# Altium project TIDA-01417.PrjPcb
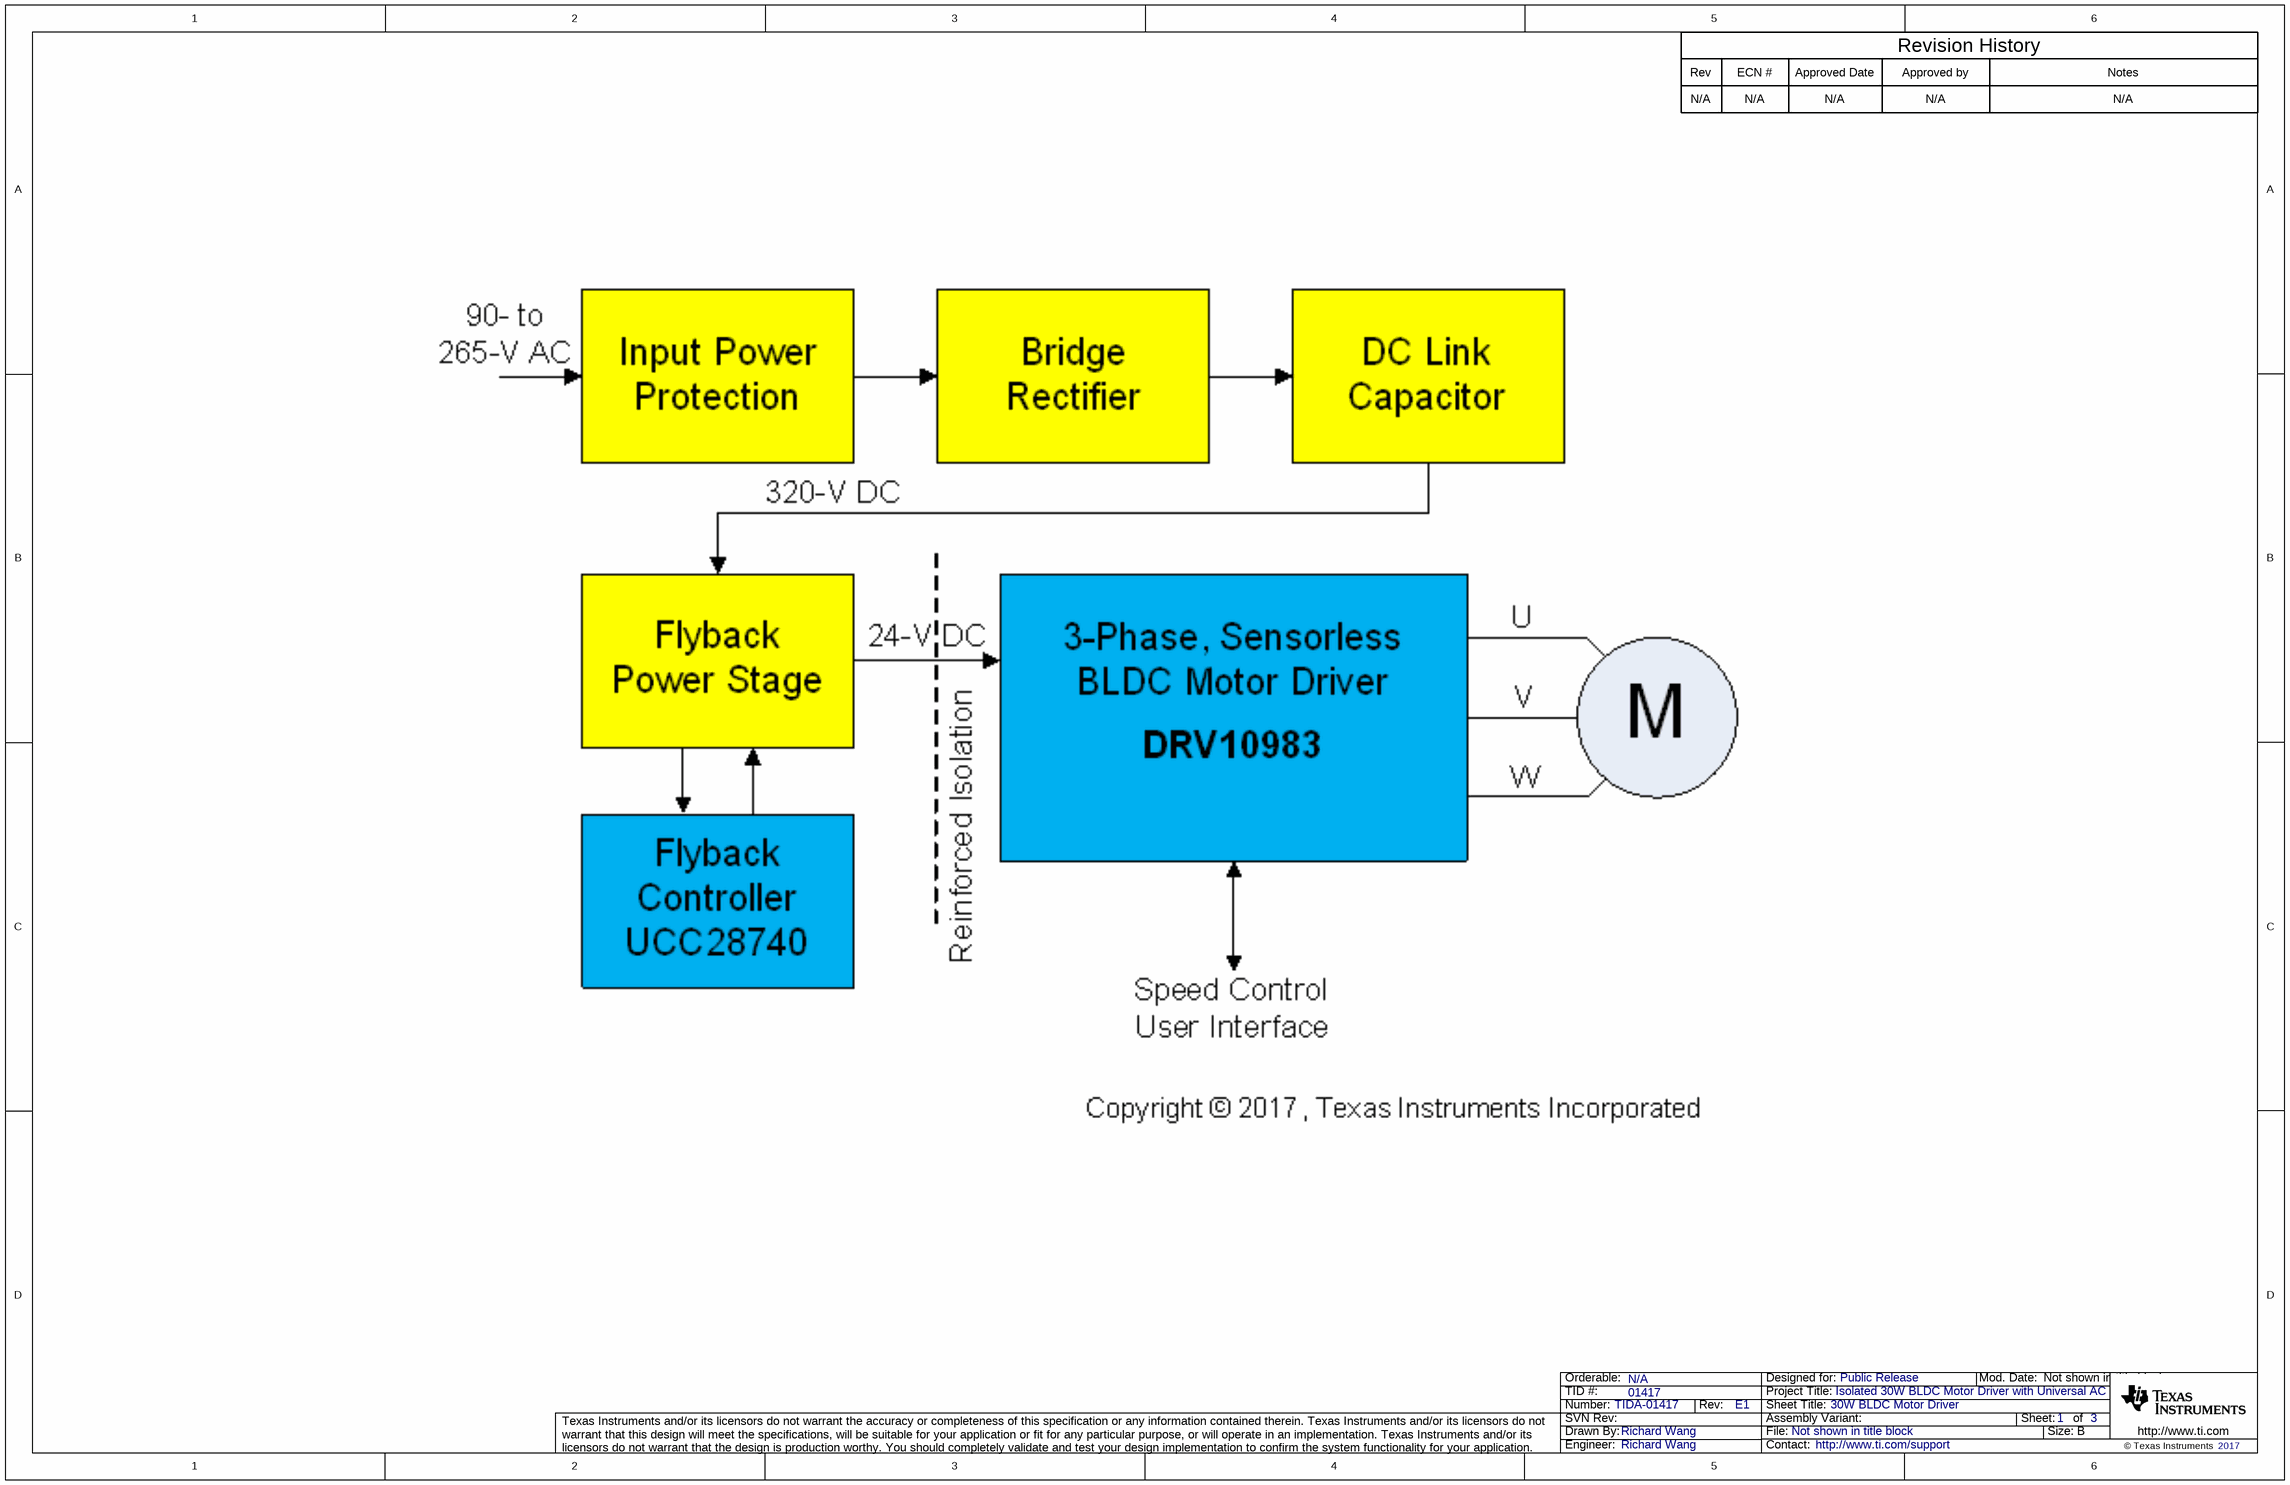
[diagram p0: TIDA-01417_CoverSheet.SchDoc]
CopyrightYear: 2017; EVM_orderable: N/A; PCB_Layout: Richard Wang; PCB_Rev: E1; PRJ_Customer: Public Release; PRJ_Engineer: Richard Wang; PRJ_Number: TIDA-01417; PRJ_Title: Isolated 30W BLDC Motor Driver with Universal AC input; SCH_Rev: E1; TechSupport: http://www.ti.com/support; TID: 01417
3 sheets, 70 parts. Net scope: flat (ports and power ports of the same name join across sheets).
Board file: TIDA-01417_PCB.PcbDoc
Sheets:
  TIDA-01417_CoverSheet.SchDoc
  TIDA-01417_BlankSheet.SchDoc
  TIDA-01417_EVM_Hardware.SchDoc

## Sheet TIDA-01417_CoverSheet.SchDoc: 30W BLDC Motor Driver
size 431 x 279 mm; Date: Not shown in title block; ApprovedBy: Not shown in title block; CheckedBy: Not shown in title block; Author: Not shown in title block; CompanyName: Not shown in title block; DrawnBy: Richard Wang; Engineer: Not shown in title block; Organization: Not shown in title block; Address1: Not shown in title block; Address2: Not shown in title block; Address3: Not shown in title block; Address4: Not shown in title block; DocumentNumber: 1; Revision: Use project parameter SCH_Rev; SheetNumber: 1; SheetTotal: 3; PageSetup: Record=PageOptions¦CenterHorizontal=True¦CenterVertical=True¦PrintScale=1.00¦XCorrection=1.00¦YCorrection=1.00¦PrintKind=0¦BorderSize=5000000¦LeftOffset=0¦BottomOffset=0¦Orientation=2¦PaperLength=1000¦PaperWidth=1000¦Scale=100¦PaperSource=15¦PrintQuality=600¦MediaType=1¦DitherType=10¦PaperKind=Letter¦PrintScaleMode=1

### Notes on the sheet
- Rev
- N/A
- ECN #
- Approved Date
- Approved by
- Revision History
- Notes

## Sheet TIDA-01417_BlankSheet.SchDoc: Isolated 30W BLDC Motor Driver
size 431 x 279 mm; Date: Not shown in title block; ApprovedBy: Not shown in title block; CheckedBy: Not shown in title block; Author: Not shown in title block; CompanyName: Not shown in title block; DrawnBy: Richard Wang; Engineer: Not shown in title block; Organization: Not shown in title block; Address1: Not shown in title block; Address2: Not shown in title block; Address3: Not shown in title block; Address4: Not shown in title block; DocumentNumber: 1; Revision: Use project parameter SCH_Rev; SheetNumber: 2; SheetTotal: 3; PageSetup: Record=PageOptions¦CenterHorizontal=True¦CenterVertical=True¦PrintScale=1.00¦XCorrection=1.00¦YCorrection=1.00¦PrintKind=0¦BorderSize=5000000¦LeftOffset=0¦BottomOffset=0¦Orientation=2¦PaperLength=1000¦PaperWidth=1000¦Scale=100¦PaperSource=15¦PrintQuality=600¦MediaType=1¦DitherType=10¦PaperKind=Letter¦PrintScaleMode=1
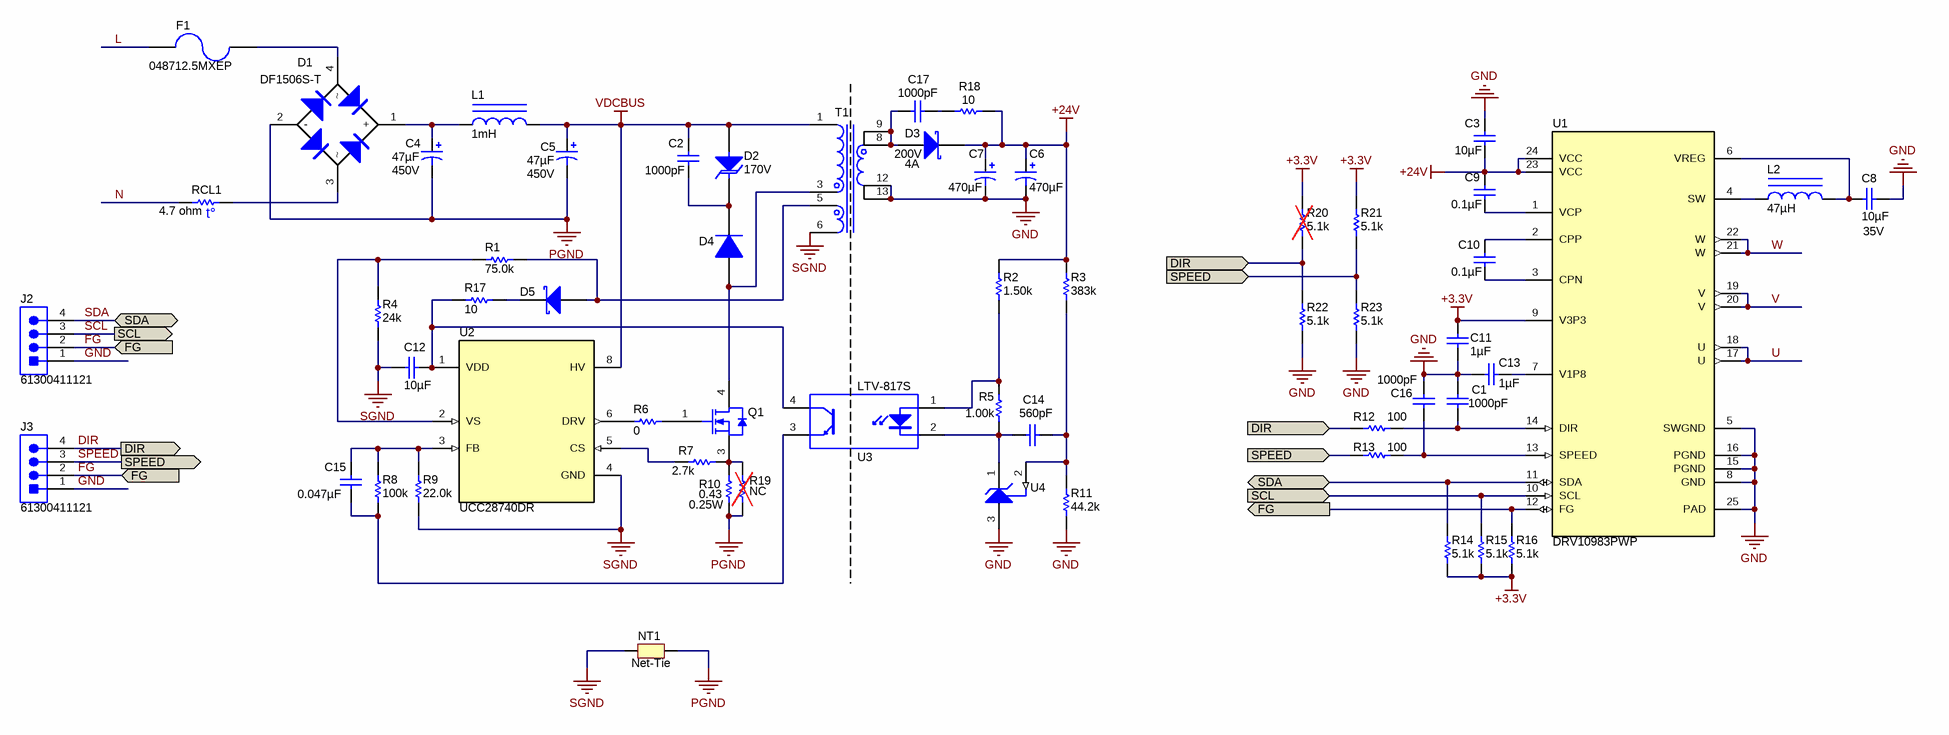
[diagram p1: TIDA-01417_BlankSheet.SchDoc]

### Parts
C1  ValueDisplayed: 1000pF  [0603]  (hidden comment: CGA3E2X7R2A102K080AA)
C2  ValueDisplayed: 1000pF  [0805_HV]  (hidden comment: C0805C102JBRACTU)
C3  ValueDisplayed: 10µF  [0805_HV]  (hidden comment: C2012X5R1V106K085AC)
C4  ValueDisplayed: 47µF  Value2: 450V  [SMG_1600x3550]  (hidden comment: ESMG451ELL470MLP1S)
C5  ValueDisplayed: 47µF  Value2: 450V  [SMG_1600x3550]  (hidden comment: ESMG451ELL470MLP1S)
C6  ValueDisplayed: 470µF  [Chemi-Con_1000x2000]  (hidden comment: ELXZ350ELL471MJ20S)
C7  ValueDisplayed: 470µF  [Chemi-Con_1000x2000]  (hidden comment: ELXZ350ELL471MJ20S)
C8  ValueDisplayed: 10µF  Value2: 35V  [0805_HV]  (hidden comment: C2012X5R1V106K085AC)
C9  ValueDisplayed: 0.1µF  [0603]  (hidden comment: C1608X5R1H104K080AA)
C10  ValueDisplayed: 0.1µF  [0603]  (hidden comment: C1608X5R1H104K080AA)
C11  ValueDisplayed: 1µF  [0603]  (hidden comment: C1608X5R1H105K080AB)
C12  ValueDisplayed: 10µF  [0805_HV]  (hidden comment: C2012X5R1V106K085AC)
C13  ValueDisplayed: 1µF  [0603]  (hidden comment: C1608X5R1H105K080AB)
C14  ValueDisplayed: 560pF  [0603]  (hidden comment: GRM188R71H561KA01D)
C15  ValueDisplayed: 0.047µF  [0603]  (hidden comment: C1608X5R1H473K080AA)
C16  ValueDisplayed: 1000pF  [0603]  (hidden comment: CGA3E2X7R2A102K080AA)
C17  ValueDisplayed: 1000pF  [0805_HV]  (hidden comment: C0805C102JBRACTU)
D1  DF1506S-T  [DF-S]
D2  value 170V  [SMB]  (hidden comment: SMBJ170A-13-F)
D3  value 200V  Value1: 4A  [SMC]  (hidden comment: MBRS4201T3G)
D4  US1M-13-F  [SMA]  (value not drawn)
D5  PMEG10010ELRX  [SOD-123W]  (value not drawn)
F1  048712.5MXEP  [Fuse_217_015_Verical]
J2  61300411121  [WURTH_61300411121]
J3  61300411121  [WURTH_61300411121]
L1  ValueDisplayed: 1mH  [WE-TI_8095]  (hidden comment: 768772102)
L2  ValueDisplayed: 47µH  [IND_CB2518]  (hidden comment: CB2518T470K)
NT1  Net-Tie  [Net-Tie_10mil]  (net tie, no BOM)
Q1  TK7P65W,RQ  [DPAK]  (value not drawn)
R1  ValueDisplayed: 75.0k  [0603]  (hidden comment: RC0603FR-0775KL)
R2  ValueDisplayed: 1.50k  [0603]  (hidden comment: RC0603FR-071K5L)
R3  ValueDisplayed: 383k  [0603]  (hidden comment: RT0603BRD07383KL)
R4  ValueDisplayed: 24k  [0603]  (hidden comment: RC0603JR-0724KL)
R5  ValueDisplayed: 1.00k  [0603]  (hidden comment: RC0603FR-071KL)
R6  ValueDisplayed: 0  [0603]  (hidden comment: MCR03EZPJ000)
R7  ValueDisplayed: 2.7k  [0603]  (hidden comment: RC0603JR-072K7L)
R8  ValueDisplayed: 100k  [0603]  (hidden comment: RC0603FR-07100KL)
R9  ValueDisplayed: 22.0k  [0603]  (hidden comment: RC0603FR-0722KL)
R10  ValueDisplayed: 0.43  Value2: 0.25W  [1206]  (hidden comment: ERJ-8RQFR43V)
R11  ValueDisplayed: 44.2k  [0603]  (hidden comment: RC0603FR-0744K2L)
R12  ValueDisplayed: 100  [0603]  (hidden comment: RC0603FR-07100RL)
R13  ValueDisplayed: 100  [0603]  (hidden comment: RC0603FR-07100RL)
R14  ValueDisplayed: 5.1k  [0603]  (hidden comment: RC0603JR-075K1L)
R15  ValueDisplayed: 5.1k  [0603]  (hidden comment: RC0603JR-075K1L)
R16  ValueDisplayed: 5.1k  [0603]  (hidden comment: RC0603JR-075K1L)
R17  ValueDisplayed: 10  [0603]  (hidden comment: CRCW060310R0JNEA)
R18  ValueDisplayed: 10  [0805_HV]  (hidden comment: RC0805JR-0710RL)
R19  NC  [1206]
R20  ValueDisplayed: 5.1k  [0603]  (hidden comment: RC0603JR-075K1L)
R21  ValueDisplayed: 5.1k  [0603]  (hidden comment: RC0603JR-075K1L)
R22  ValueDisplayed: 5.1k  [0603]  (hidden comment: RC0603JR-075K1L)
R23  ValueDisplayed: 5.1k  [0603]  (hidden comment: RC0603JR-075K1L)
RCL1  value 4.7 ohm  [THERM_B57236S0]  (hidden comment: B57236S479M)
T1  750343466  [PCBComponent_1]  (value not drawn)
U1  DRV10983PWP  [PWP0024B_N]
U2  UCC28740DR  [D0007A_N]
U3  LTV-817S  [DIP254P762X350-4]
U4  TL431BQDBZT  [DBZ0003A_N]  (value not drawn)

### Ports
DIR (in), DIR (out), FG (in), FG (out), SCL (in), SCL (out), SDA (bidir), SPEED (in), SPEED (out)

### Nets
+3.3V: C11.2 R14.1 R15.1 R16.1 R20.2 R21.2 U1.9(V3P3)
+24V: C3.2 C6.1(+) C7.1(+) C9.2 D3.1(K) R2.2 R3.2 R18.2 U1.23(VCC) U1.24(VCC)
GND: C1.1 C3.1 C6.2(-) C7.2(-) C8.1 C11.1 C13.1 C16.1 J2.1 J3.1 R11.1 R22.1 R23.1 T1.12 T1.13 U1.5(SWGND) U1.8(GND) U1.15(PGND) U1.16(PGND) U1.25(PAD) U4.3(ANODE)
PGND: C4.2(-) C5.2(-) D1.2(-) NT1.2 R10.1 R19.1
SGND: C12.1 NT1.1 R4.1 R9.1 T1.6 U2.4(GND)
VDCBUS: C2.1 C5.1(+) D2.2(A) L1.2 T1.1 U2.8(HV)
DIR: J3.4 R12.1 R20.1 R22.2 ; port DIR
FG: J2.2 J3.2 R16.2 U1.12(FG) ; port FG
L: F1.1
N: RCL1.1
SCL: J2.3 R15.2 U1.10(SCL) ; port SCL
SDA: J2.4 R14.2 U1.11(SDA) ; port SDA
SPEED: J3.3 R13.1 R21.1 R23.2 ; port SPEED
U: U1.17(U) U1.18(U)
V: U1.19(V) U1.20(V)
W: U1.21(W) U1.22(W)
NetC1_2: C1.2 R12.2 U1.14(DIR)
NetC2_2: C2.2 D2.1(K) D4.1(K)
NetC4_1: C4.1(+) D1.1(+) L1.1
NetC8_2: C8.2 L2.2 U1.6(VREG)
NetC9_1: C9.1 U1.1(VCP)
NetC10_1: C10.1 U1.2(CPP)
NetC10_2: C10.2 U1.3(CPN)
NetC12_2: C12.2 R17.1 U2.1(VDD) U3.4(C)
NetC13_2: C13.2 U1.7(V1P8)
NetC14_1: C14.1 R3.1 R11.2 U4.2(REF)
NetC14_2: C14.2 R5.1 U3.2(K) U4.1(CATHODE)
NetC15_1: C15.1 R8.2 R9.2 U2.3(FB)
NetC15_2: C15.2 R8.1 U3.3(E)
NetC16_2: C16.2 R13.2 U1.13(SPEED)
NetC17_1: C17.1 D3.2(A) T1.8 T1.9
NetC17_2: C17.2 R18.1
NetD1_3: D1.3 RCL1.2
NetD1_4: D1.4 F1.2
NetD4_2: D4.2(A) Q1.4(D) T1.3
NetD5_1: D5.1(K) R17.2
NetD5_2: D5.2(A) R1.2 T1.5
NetL2_1: L2.1 U1.4(SW)
NetQ1_1: Q1.1(G) R6.2
NetQ1_3: Q1.3(S) R7.2 R10.2 R19.2
NetR1_1: R1.1 R4.2 U2.2(VS)
NetR2_1: R2.1 R5.2 U3.1(A)
NetR6_1: R6.1 U2.6(DRV)
NetR7_1: R7.1 U2.5(CS)

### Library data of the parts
C1 C16 = CGA3E2X7R2A102K080AA: CAP, CERM, 1000 pF, 100 V, +/- 10%, X7R, AEC-Q200 Grade 1, 0603; Manufacturer: TDK; Polarized: N; CompType: Capacitor; Value: 1000pF; U/M: EA; Cap_F: 0.000000001; Tolerance_%: 10; ESR_ohm: 1.97137; Value1: 1.97137 ohm; VDC_V: 100; Value2: 100V; IRMS_A: 0.305705; TaMin_C: -55; TaMax_C: 125; SizeArea_mm2: 1.28; SizeAreaWB_mm2: 4.68; SizeX_mm: 1.6; SizeY_mm: 0.8; SizeZ_mm: 1; AEC Category: Q200; AEC Qualified: Y
C2 C17 = C0805C102JBRACTU: CAP, CERM, 1000 pF, 630 V, +/- 5%, X7R, 0805; Manufacturer: Kemet; Polarized: N; CompType: Capacitor; Value: 1000pF; U/M: EA; Cap_F: 0.000000001; Tolerance_%: 5; Value1: Unknown; VDC_V: 630; Value2: 630V; TaMin_C: -55; TaMax_C: 125; Cap_Case: 0805; SizeArea_mm2: 2.5; SizeAreaWB_mm2: 6.75; SizeX_mm: 2; SizeY_mm: 1.25; SizeZ_mm: 1.45; AEC Category: Q200
C3 C12 = C2012X5R1V106K085AC: CAP, CERM, 10 µF, 35 V, +/- 10%, X5R, 0805; Manufacturer: TDK; Polarized: N; CompType: Capacitor; Value: 10uF; U/M: EA; Cap_F: 0.00001; Tolerance_%: 10; ESR_ohm: 0.002818; Value1: 0.002818 ohm; VDC_V: 35; Value2: 35V; IRMS_A: 3.88676; TaMin_C: -55; TaMax_C: 85; Cap_Case: 0805; SizeArea_mm2: 2.5; SizeAreaWB_mm2: 6.75; SizeX_mm: 2; SizeY_mm: 1.25; SizeZ_mm: 1.45; AEC Category: Q200
C4 C5 = ESMG451ELL470MLP1S: CAP, AL, 47 µF, 450 V, +/- 20%, TH; Manufacturer: Chemi-Con; Polarized: Y; CompType: Capacitor; Value: 47uF; U/M: EA; Cap_F: 0.000047; Tolerance_%: 20; Value1: Unknown; VDC_V: 450; IRMS_A: 0.265; TaMin_C: -25; TaMax_C: 85; Cap_Case: 16x35.5mm; SizeAreaWB_mm2: 324; SizeArea_mm2: 256; SizeX_mm: 16; SizeZ_mm: 37; AEC Category: Q200; AEC Qualified: N
C6 C7 = ELXZ350ELL471MJ20S: CAP, AL, 470 µF, 35 V, +/- 20%, AEC-Q200 Grade 2, TH; Manufacturer: Chemi-Con; Polarized: Y; CompType: Capacitor; Value: 470uF; U/M: EA; Cap_F: 0.00047; Tolerance_%: 20; Value1: Unknown; VDC_V: 35; Value2: 35V; IRMS_A: 1.22; TaMin_C: -55; TaMax_C: 105; Cap_Case: 10x20mm; SizeAreaWB_mm2: 144; SizeArea_mm2: 100; SizeX_mm: 10; SizeZ_mm: 21.5; AEC Category: Q200; AEC Grade: 2
C8 = C2012X5R1V106K085AC: CAP, CERM, 10 µF, 35 V, +/- 10%, X5R, 0805; Manufacturer: TDK; Polarized: N; CompType: Capacitor; Value: 10uF; U/M: EA; Cap_F: 0.00001; Tolerance_%: 10; ESR_ohm: 0.002818; Value1: 0.002818 ohm; VDC_V: 35; IRMS_A: 3.88676; TaMin_C: -55; TaMax_C: 85; Cap_Case: 0805; SizeArea_mm2: 2.5; SizeAreaWB_mm2: 6.75; SizeX_mm: 2; SizeY_mm: 1.25; SizeZ_mm: 1.45; AEC Category: Q200
C9 C10 = C1608X5R1H104K080AA: CAP, CERM, 0.1 µF, 50 V, +/- 10%, X5R, 0603; Manufacturer: TDK; Polarized: N; CompType: Capacitor; Value: 0.1uF; U/M: EA; Cap_F: 0.0000001; Tolerance_%: 10; ESR_ohm: 0.0296; Value1: 0.0296 ohm; VDC_V: 50; Value2: 50V; IRMS_A: 0.97199; TaMin_C: -55; TaMax_C: 85; SizeArea_mm2: 1.28; SizeAreaWB_mm2: 4.68; SizeX_mm: 1.6; SizeY_mm: 0.8; SizeZ_mm: 1; AEC Category: Q200
C11 C13 = C1608X5R1H105K080AB: CAP, CERM, 1 µF, 50 V, +/- 10%, X5R, 0603; Manufacturer: TDK; Polarized: N; CompType: Capacitor; Value: 1uF; U/M: EA; Cap_F: 0.000001; Tolerance_%: 10; ESR_ohm: 0.005522; Value1: 0.005522 ohm; VDC_V: 50; Value2: 50V; IRMS_A: 2.21617; TaMin_C: -55; TaMax_C: 85; SizeArea_mm2: 1.28; SizeAreaWB_mm2: 4.68; SizeX_mm: 1.6; SizeY_mm: 0.8; SizeZ_mm: 1; AEC Category: Q200
C14 = GRM188R71H561KA01D: CAP, CERM, 560 pF, 50 V, +/- 10%, X7R, 0603; Manufacturer: MuRata; Polarized: N; CompType: Capacitor; Value: 560pF; U/M: EA; Cap_F: 0.00000000056; Tolerance_%: 10; Value1: Unknown; VDC_V: 50; Value2: 50V; TaMin_C: -55; TaMax_C: 125; SizeArea_mm2: 1.28; SizeAreaWB_mm2: 4.68; SizeX_mm: 1.6; SizeY_mm: 0.8; SizeZ_mm: 1; AEC Category: Q200
C15 = C1608X5R1H473K080AA: CAP, CERM, 0.047 µF, 50 V, +/- 10%, X5R, 0603; Manufacturer: TDK; Polarized: N; CompType: Capacitor; Value: 0.047uF; U/M: EA; Cap_F: 0.000000047; Tolerance_%: 10; ESR_ohm: 0.049007; Value1: 0.049007 ohm; VDC_V: 50; Value2: 50V; IRMS_A: 0.767528; TaMin_C: -55; TaMax_C: 85; SizeArea_mm2: 1.28; SizeAreaWB_mm2: 4.68; SizeX_mm: 1.6; SizeY_mm: 0.8; SizeZ_mm: 1; AEC Category: Q200
D1 = DF1506S-T: Diode, Switching-Bridge, 600 V, 1.5 A, DF-S; Manufacturer: Diodes Inc.; U/M: EA; Vf_V: 1.1; Value: 600V; Value1: 1.5A; Value2: 1.1V; Io_A: 1.5; Vr_V: 600; TJmax_C: 150; SizeAreaWB_mm2: 98.794; SizeArea_mm2: 62.974; SizeX_mm: 7.4; SizeY_mm: 8.51; SizeZ_mm: 3.4; AEC Category: Q101
D2 = SMBJ170A-13-F: Diode, TVS, Uni, 170 V, 275 Vc, SMB; Manufacturer: Diodes Inc.; U/M: EA; Power_W: 5; Vr_V: 170; Value1: 5W; SizeAreaWB_mm2: 44.156; SizeArea_mm2: 21.336; SizeX_mm: 5.6; SizeY_mm: 3.81; SizeZ_mm: 2.6; AEC Category: Q101
D3 = MBRS4201T3G: Diode, Schottky, 200 V, 4 A, SMC; Manufacturer: ON Semiconductor; U/M: EA; Vf_V: 0.86; Value2: 0.86V; Io_A: 4; Vr_V: 200; TJmax_C: 150; SizeAreaWB_mm2: 83.2686; SizeArea_mm2: 50.5686; SizeX_mm: 8.13; SizeY_mm: 6.22; SizeZ_mm: 2.6; AEC Category: Q101
D4 = US1M-13-F: Diode, Ultrafast, 1000 V, 1 A, SMA; Manufacturer: Diodes Inc.; U/M: EA; Vf_V: 1.7; Value: 1000V; Value1: 1A; Value2: 1.7V; Io_A: 1; Vr_V: 1000; TJmax_C: 150; RJC_CperW: 30; SizeAreaWB_mm2: 37.3428; SizeArea_mm2: 16.3228; SizeX_mm: 5.59; SizeY_mm: 2.92; SizeZ_mm: 2.87; AEC Category: Q101
D5 = PMEG10010ELRX: Diode, Schottky, 100 V, 1 A, AEC-Q101, SOD-123W; Manufacturer: NXP Semiconductor; U/M: EA; Vf_V: 0.77; Value: 100V; Value1: 1A; Value2: 0.77V; Io_A: 1; Vr_V: 100; TJmax_C: 175; SizeAreaWB_mm2: 12.15; SizeArea_mm2: 5.95; SizeX_mm: 3.5; SizeY_mm: 1.7; AEC Category: Q101; AEC Qualified: Y
F1 = 0217015.MXEP: FUSE 420VAC/DC 5X20 FA PT 12.5A; Manufacturer: Littelfuse; VDC_V: 250; Irating_A: 8; Rtyp_Ohm: 0.04; MeltingTyp: 617.135
J2 J3 = 61300411121: Header, 2.54 mm, 4x1, Gold, TH; Manufacturer: Wurth Elektronik; SymbolCreator: a0412235
L1 = 768772102: Inductor, Shielded Drum Core, Metal Composite, 1 mH, 0.5 A, 1.7 ohm, TH; Manufacturer: Wurth Elektronik; Value: 1mH; Ind_H: 1.0E-3; Imax_A: 0.5; Irms: 0.5A @ 40C rise; Isat: 0.55A @ 10% inductance drop; DCR_ohm: 1.7; Value1: 1.7 ohm; Value2: 0.5A; SizeAreaWB_mm2: 96.04; SizeArea_mm2: 60.84; SizeX_mm: 7.8; SizeZ_mm: 10; AEC Category: Q200
L2 = CB2518T470K: Inductor, Wirewound, Ferrite, 47 µH, 0.11 A, 1.235 ohm, SMD; Manufacturer: Taiyo Yuden; Value: 47uH; Ind_H: 47.0E-6; Imax_A: 0.11; Irms: 0.42A @ 40C rise; Isat: 0.11A @ 30% inductance drop; DCR_ohm: 1.235; Value2: 0.11A; SizeAreaWB_mm2: 9.8; SizeArea_mm2: 4.5; SizeX_mm: 2.5; SizeY_mm: 1.8; SizeZ_mm: 2; AEC Category: Q200
NT1 = Net-Tie: Single point connection between nets.; SymbolCreator: codlsc
Q1 = SPD04N80C3: MOSFET, N-CH, 800 V, 4 A, DPAK; Manufacturer: Infineon Technologies; Alternate Manufacturer: None; U/M: EA; ChType: N; Value: 650V; VdsMax_V: 650; Value1: 0.8 ohm; Rdson45_ohm: 1.3; Value2: 15 nC; QgTyp_nC: 26; Vgs_V: 3.5; IdsMax_A: 6.8A; SizeAreaWB_mm2: 101.7114; SizeArea_mm2: 64.8114; SizeX_mm: 9.91; SizeY_mm: 6.54; SizeZ_mm: 2.29; AEC Category: Q101
R1 = RC0603FR-0775KL: RES, 75.0 k, 1%, 0.1 W, 0603; Manufacturer: Yageo America; CompType: Resistor; Value: 75.0k; Res_ohm: 75000; Value_Code: 75k0; Tolerance_%: 1; Power_W: 0.1; Value2: 0.1W; VDC_V: 150; TempCo: 200 ppm/C; SizeArea_mm2: 1.28; SizeX_mm: 1.6; SizeY_mm: 0.8; EIA_Code: E96; U/M: EA; AEC Category: Q200
R2 = RC0603FR-071K5L: RES, 1.50 k, 1%, 0.1 W, 0603; Manufacturer: Yageo America; CompType: Resistor; Value: 1.50k; Res_ohm: 1500; Value_Code: 1k50; Tolerance_%: 1; Power_W: 0.1; Value2: 0.1W; VDC_V: 150; TempCo: 200 ppm/C; SizeArea_mm2: 1.28; SizeX_mm: 1.6; SizeY_mm: 0.8; EIA_Code: E96; U/M: EA; AEC Category: Q200
R3 = RT0603BRD07383KL: RES, 383 k, 0.1%, 0.1 W, 0603; Manufacturer: Yageo America; CompType: Resistor; Value: 383k; Res_ohm: 383000; Tolerance_%: 0.1; Value2: 0.1W; VDC_V: 75; TempCo: 25 ppm/C; SizeArea_mm2: 1.28; SizeX_mm: 1.6; SizeY_mm: 0.8; SizeZ_mm: 1; EIA_Code: E192; U/M: EA; AEC Category: Q200
R4 = RC0603JR-0724KL: RES, 24 k, 5%, 0.1 W, 0603; Manufacturer: Yageo America; CompType: Resistor; Value: 24k; Res_ohm: 24000; Value_Code: 24k0; Tolerance_%: 5; Power_W: 0.1; Value2: 0.1W; VDC_V: 50; TempCo: 100 ppm/C; SizeArea_mm2: 1.28; SizeX_mm: 1.6; SizeY_mm: 0.8; SizeZ_mm: 1; EIA_Code: E24; U/M: EA; AEC Category: Q200
R5 = RC0603FR-071KL: RES, 1.00 k, 1%, 0.1 W, 0603; Manufacturer: Yageo America; CompType: Resistor; Value: 1.00k; Res_ohm: 1000; Value_Code: 1k00; Tolerance_%: 1; Power_W: 0.1; Value2: 0.1W; VDC_V: 150; TempCo: 200 ppm/C; SizeArea_mm2: 1.28; SizeX_mm: 1.6; SizeY_mm: 0.8; EIA_Code: E96; U/M: EA; AEC Category: Q200
R6 = MCR03EZPJ000: RES, 0, 5%, 0.1 W, 0603; Manufacturer: Rohm; CompType: Resistor; Value: 0; Value_Code: 0000; Tolerance_%: 5; Power_W: 0.1; Value2: 0.1W; TempCo: ppm/C; SizeArea_mm2: 1.28; SizeX_mm: 1.6; SizeY_mm: 0.8; SizeZ_mm: 1; EIA_Code: E24; U/M: EA; AEC Category: Q200; AEC Qualified: N
R7 = RC0603JR-072K7L: RES, 2.7 k, 5%, 0.1 W, 0603; Manufacturer: Yageo America; CompType: Resistor; Value: 2.7k; Res_ohm: 2700; Value_Code: 2k70; Tolerance_%: 5; Power_W: 0.1; Value2: 0.1W; VDC_V: 50; TempCo: 100 ppm/C; SizeArea_mm2: 1.28; SizeX_mm: 1.6; SizeY_mm: 0.8; SizeZ_mm: 1; EIA_Code: E24; U/M: EA; AEC Category: Q200
R8 = RC0603FR-07100KL: RES, 100 k, 1%, 0.1 W, 0603; Manufacturer: Yageo America; CompType: Resistor; Value: 100k; Res_ohm: 100000; Tolerance_%: 1; Power_W: 0.1; Value2: 0.1W; VDC_V: 150; TempCo: 200 ppm/C; SizeArea_mm2: 1.28; SizeX_mm: 1.6; SizeY_mm: 0.8; EIA_Code: E96; U/M: EA; AEC Category: Q200
R9 = RC0603FR-0722KL: RES, 22.0 k, 1%, 0.1 W, 0603; Manufacturer: Yageo America; CompType: Resistor; Value: 22.0k; Res_ohm: 22000; Value_Code: 22k0; Tolerance_%: 1; Power_W: 0.1; Value2: 0.1W; VDC_V: 150; TempCo: 200 ppm/C; SizeArea_mm2: 1.28; SizeX_mm: 1.6; SizeY_mm: 0.8; U/M: EA; AEC Category: Q200
R10 = ERJ-8RQFR43V: RES, 0.43, 1%, 0.25 W, AEC-Q200 Grade 1, 1206; Manufacturer: Panasonic; CompType: Resistor; Value: 0.43; Value_Code: R430; Tolerance_%: 1; Power_W: 0.25; TempCo: 250 ppm/C; SizeArea_mm2: 5.12; SizeX_mm: 3.2; SizeY_mm: 1.6; SizeZ_mm: 1.35; EIA_Code: E96; U/M: EA; AEC Category: Q200; AEC Qualified: Y
R11 = RC0603FR-0744K2L: RES, 44.2 k, 1%, 0.1 W, 0603; Manufacturer: Yageo America; CompType: Resistor; Value: 44.2k; Res_ohm: 44200; Value_Code: 44k2; Tolerance_%: 1; Power_W: 0.1; Value2: 0.1W; VDC_V: 150; TempCo: 200 ppm/C; SizeArea_mm2: 1.28; SizeX_mm: 1.6; SizeY_mm: 0.8; EIA_Code: E96; U/M: EA; AEC Category: Q200
R12 R13 = RC0603FR-07100RL: RES, 100, 1%, 0.1 W, 0603; Manufacturer: Yageo America; CompType: Resistor; Value: 100; Value_Code: 100R; Tolerance_%: 1; Power_W: 0.1; Value2: 0.1W; VDC_V: 150; TempCo: 200 ppm/C; SizeArea_mm2: 1.28; SizeX_mm: 1.6; SizeY_mm: 0.8; EIA_Code: E96; U/M: EA; AEC Category: Q200
R14-R16 R20-R23 = RC0603JR-075K1L: RES, 5.1 k, 5%, 0.1 W, 0603; Manufacturer: Yageo America; CompType: Resistor; Value: 5.1k; Res_ohm: 5100; Value_Code: 5k10; Tolerance_%: 5; Power_W: 0.1; Value2: 0.1W; VDC_V: 50; TempCo: 100 ppm/C; SizeArea_mm2: 1.28; SizeX_mm: 1.6; SizeY_mm: 0.8; SizeZ_mm: 1; EIA_Code: E24; U/M: EA; AEC Category: Q200
R17 = CRCW060310R0JNEA: RES, 10, 5%, 0.1 W, 0603; Manufacturer: Vishay-Dale; CompType: Resistor; Value: 10; Value_Code: 10R0; Tolerance_%: 5; Power_W: 0.1; Value2: 0.1W; VDC_V: 75; TempCo: 200 ppm/C; SizeArea_mm2: 1.28; SizeX_mm: 1.6; SizeY_mm: 0.8; SizeZ_mm: 1; EIA_Code: E24; U/M: EA; AEC Category: Q200
R18 = RC0805JR-0710RL: RES, 10, 5%, 0.125 W, 0805; Manufacturer: Yageo America; CompType: Resistor; Value: 10; Value_Code: 10R0; Tolerance_%: 5; Power_W: 0.125; Value2: 0.125W; VDC_V: 150; TempCo: 200 ppm/C; SizeArea_mm2: 2.5; SizeX_mm: 2; SizeY_mm: 1.25; SizeZ_mm: 1.45; EIA_Code: E24; U/M: EA; AEC Category: Q200
R19 = ERJ-8RQFR82V: RES, 0.82, 1%, 0.25 W, 1206; Manufacturer: Panasonic; CompType: Resistor; Value: 0.82; Value_Code: R820; Tolerance_%: 1; Power_W: 0.25; Value2: 0.25W; TempCo: 250 ppm/C; SizeArea_mm2: 5.12; SizeX_mm: 3.2; SizeY_mm: 1.6; SizeZ_mm: 1.35; EIA_Code: E96; U/M: EA; AEC Category: Q200
RCL1 = B57236S0100M000: ICL 4.7 OHM 20% 4.6A 11.51MM; Manufacturer: EPCOS (TDK); CompType: ThermistorNTC; Tolerance_%: 20; Power_W: 2.1; U/M: EA; TaMin_C: -55; TaMax_C: 170
T1 = 36W24V: Transformer, PRI inductance 280uH, reinforced isolation; Manufacturer: Wurth Elektronik; SymbolVersion: use current date i.e. 2008-05-20; SymbolCreator: Use a-id; CompType: Used in some BOM reports.  Useful for finding later.; U/M: EA, IN, or GM
U1 = DRV10983PWP: 12- to 24-V, Three-Phase, Sensorless BLDC Motor Driver, PWP0024B (TSSOP-24); Manufacturer: Texas Instruments; SymbolCreator: a0411947; SizeArea_mm2: 49.92; SizeAreaWB_mm2: 82.32; SizeX_mm: 6.4; SizeY_mm: 7.8; SizeZ_mm: 1.2; CompType: IC; U/M: EA
U2 = UCC28740DR: Constant-Voltage, Constant-Current Flyback Controller Using Opto-Coupler Feedback, D0007A (SOIC-7); Manufacturer: Texas Instruments; SymbolCreator: a0412235; SizeArea_mm2: 29.4; SizeAreaWB_mm2: 55.2; SizeX_mm: 6; SizeY_mm: 4.9; SizeZ_mm: 1.75; CompType: IC; U/M: EA
U3 = LTV-817S: Optocoupler, 5 kV, 50-600% CTR, SMT; Manufacturer: Lite-On; CTR (Min): 50%; CTR (Max): 600%; Voltage_Isolation_Vrms: 5000V; SizeAreaWB_mm2: 80.256; SizeArea_mm2: 46.736; SizeX_mm: 10.16; SizeY_mm: 4.6
U4 = TL431BQDBZT: Adjustable Precision Shunt Regulator, 34 ppm / degC, 100 mA, -40 to 125 degC, 3-pin SOT-23 (DBZ), Green (RoHS & no Sb/Br); Manufacturer: Texas Instruments; Alternate PartNumber: Equivalent; Initial Accuracy @ 25/deg C(%): 0.5; Iout/Iz(Max)(mA): 100; Min Iz for Regulation(uA): 600; Rating: Catalog; SubFamily: Shunt Voltage Reference; Temp Coeff(Max)(ppm/ degree C): 92; Temp Coeff(Typ)(ppm/ degree C): 34; VO Adj(Max)(V): 36; VO Adj(Min)(V): 2.495

## Sheet TIDA-01417_EVM_Hardware.SchDoc
size 431 x 279 mm; Date: Not shown in title block; ApprovedBy: Not shown in title block; CheckedBy: Not shown in title block; Author: Not shown in title block; CompanyName: Not shown in title block; Engineer: Not shown in title block; Organization: Not shown in title block; Address1: Not shown in title block; Address2: Not shown in title block; Address3: Not shown in title block; Address4: Not shown in title block; DocumentNumber: 1; Revision: Use project parameter SCH_Rev; SheetNumber: 3; SheetTotal: 3; PageSetup: Record=PageOptions¦CenterHorizontal=True¦CenterVertical=True¦PrintScale=1.00¦XCorrection=1.00¦YCorrection=1.00¦PrintKind=0¦BorderSize=5000000¦LeftOffset=0¦BottomOffset=0¦Orientation=2¦PaperLength=1000¦PaperWidth=1000¦Scale=100¦PaperSource=15¦PrintQuality=600¦MediaType=1¦DitherType=10¦PaperKind=Letter¦PrintScaleMode=1
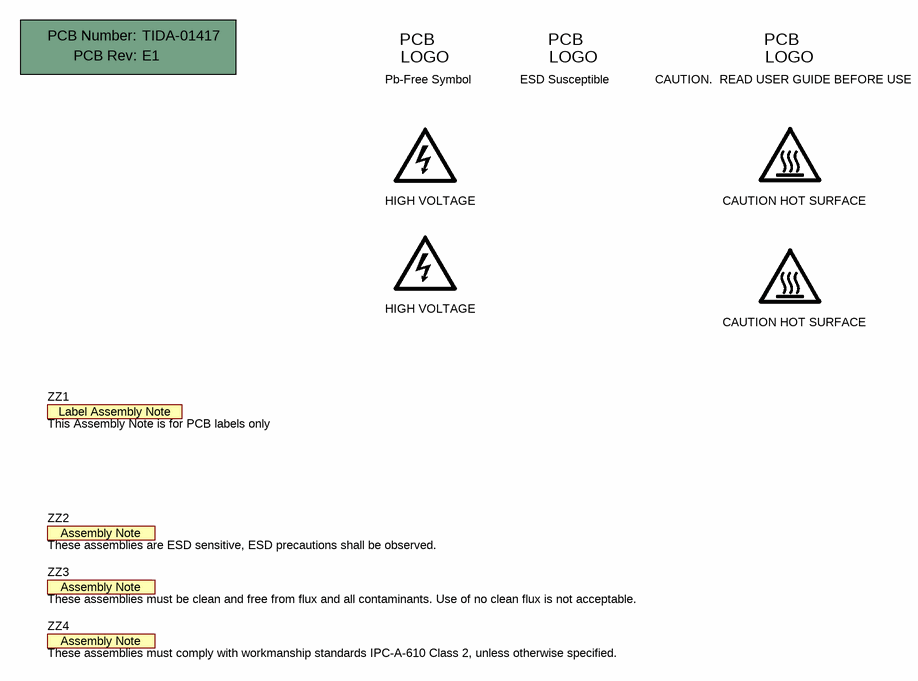
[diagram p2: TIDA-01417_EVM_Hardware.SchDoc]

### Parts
3  CAUTION HOT SURFACE  [IEC_HotSurface_small]  (no BOM)
4  CAUTION HOT SURFACE  [IEC_HotSurface_small]  (no BOM)
5  HIGH VOLTAGE  [IEC_HighVoltage_small]  (no BOM)
6  HIGH VOLTAGE  [IEC_HighVoltage_small]  (no BOM)
!PCB  Printed Circuit Board  (value not drawn)  (mechanical)
Caution  CAUTION.  READ USER GUIDE BEFORE USE  [IEC_Caution_small]  (no BOM)
ESD  ESD Susceptible  [ESD_Overlay_small]  (no BOM)
Pb  Pb-Free Symbol  [Pb-Free_Overlay_Small]  (no BOM)
ZZ1  This Assembly Note is for PCB labels only  [AssemblyNoteLabel]  (no BOM)
ZZ2  These assemblies are ESD sensitive, ESD precautions shall be observed.  [AssemblyNote]  (no BOM)
ZZ3  These assemblies must be clean and free from flux and all contaminants. Use of no clean flux is not acceptable.  [AssemblyNote]  (no BOM)
ZZ4  These assemblies must comply with workmanship standards IPC-A-610 Class 2, unless otherwise specified.  [AssemblyNote]  (no BOM)

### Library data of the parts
3 4 = IEC_HotSurface: IEC 61010-1 Hot Surface Warning; SymbolCreator: a0412235
5 6 = IEC_HighVoltage: IEC 61010-1 High Voltage Warning; SymbolCreator: a0412235
!PCB = PCB: Manufacturer: Any; PartNumber: TIDA-01417; SymbolCreator: a0412235
Caution = IEC_Caution: IEC 61010-1 Caution Warning; SymbolCreator: a0412235
ESD = ESD_Susceptible: ESD Susceptible Symbol; SymbolCreator: a0412235
Pb = Pb-Free: SymbolCreator: a0412235
ZZ1 = AssemblyNoteLabel: SymbolCreator: a0412235
ZZ2-ZZ4 = AssemblyNote: SymbolCreator: codlsc

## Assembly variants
001: not fitted FID1 FID2 FID3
